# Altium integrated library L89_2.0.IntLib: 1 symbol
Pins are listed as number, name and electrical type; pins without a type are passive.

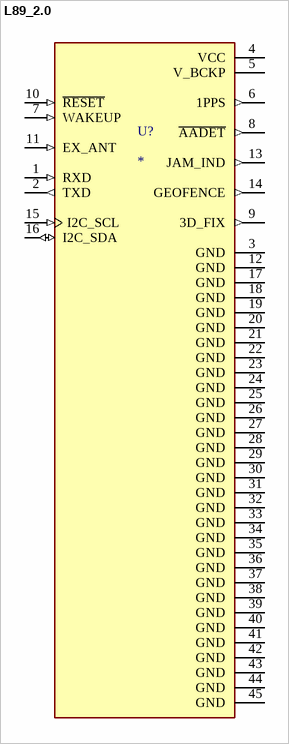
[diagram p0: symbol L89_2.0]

## L89_2.0
designator U?
L89 is a high performance IRNSS-enabled GNSS module, capable of acquiring and tracing GPS, IRNSS, GLONASS, BeiDou, Galileo and QZSS signals.; MF: Quectel; MP: L89 2.0
footprint XCVR_L89_2.0
pins: 1 RXD (in), 2 TXD (out), 3 GND (power), 4 VCC (power), 5 V_BCKP (power), 6 1PPS (out), 7 WAKEUP (in), 8 ~{AADET} (out), 9 3D_FIX (out), 10 ~{RESET} (in), 11 EX_ANT (in), 12 GND (power), 13 JAM_IND (out), 14 GEOFENCE (out), 15 I2C_SCL (in), 16 I2C_SDA (io), 17 GND (power), 18 GND (power), 19 GND (power), 20 GND (power), 21 GND (power), 22 GND (power), 23 GND (power), 24 GND (power), 25 GND (power), 26 GND (power), 27 GND (power), 28 GND (power), 29 GND (power), 30 GND (power), 31 GND (power), 32 GND (power), 33 GND (power), 34 GND (power), 35 GND (power), 36 GND (power), 37 GND (power), 38 GND (power), 39 GND (power), 40 GND (power), 41 GND (power), 42 GND (power), 43 GND (power), 44 GND (power), 45 GND (power)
